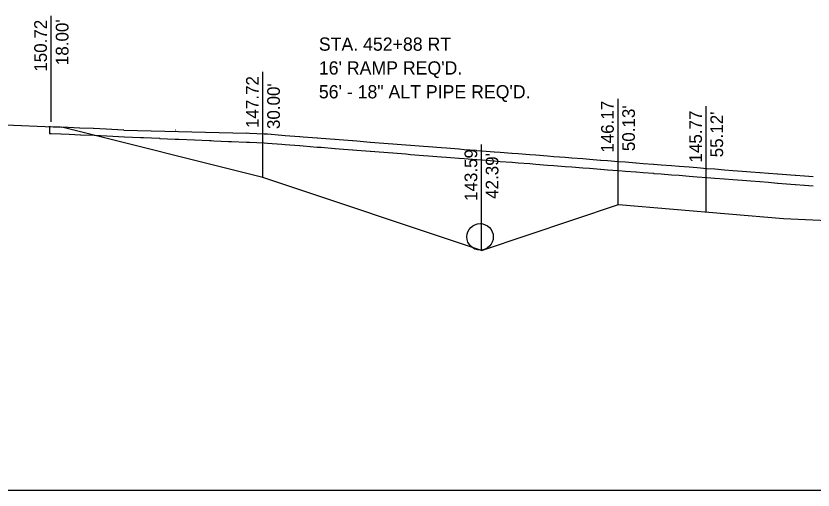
# Model space of a CAD drawing. Extents: x -100 to 4303, y -13 to 10775.
# Drawn here: x 165.99 to 211.18, y 1500 to 1526.88 of the extents above; entities that cross this region are included whole.
import ezdxf

# ---------------------------------------------------------------- set-up
doc = ezdxf.new("R2010")
doc.units = 0
for name, color, linetype in [('DTM_X_GROUND', 7, 'Continuous'), ('XS_CELL', 7, 'Continuous'), ('XS_P_DRAINAGE', 7, 'Continuous'), ('XS_P_TX_CLEARZONE', 7, 'Continuous')]:
    doc.layers.add(name, color=color, linetype=linetype)

msp = doc.modelspace()

# ---------------------------------------------------------------- linework, layer by layer
at = {"layer": 'DTM_X_GROUND'}
for p, q in [((164, 1520.754), (168.551, 1520.572)), ((167.86, 1520.599), (167.859, 1520.599)), ((167.953, 1520.596), (167.86, 1520.599)), ((167.906, 1520.598), (167.906, 1520.222)), ((168.497, 1520.574), (167.953, 1520.596)), ((167.953, 1520.596), (167.953, 1520.596)), ((167.906, 1520.222), (167.907, 1520.222)), ((167.907, 1520.222), (168, 1520.218)), ((168, 1520.218), (168, 1520.218)), ((168, 1520.218), (168.544, 1520.196)), ((168.504, 1520.574), (168.497, 1520.574)), ((168.959, 1520.555), (168.504, 1520.574)), ((168.544, 1520.196), (168.551, 1520.196)), ((168.551, 1520.196), (169.006, 1520.178)), ((169.607, 1520.522), (168.959, 1520.555)), ((169.006, 1520.178), (169.654, 1520.145)), ((169.619, 1520.521), (169.607, 1520.522)), ((170.375, 1520.49), (169.619, 1520.521)), ((169.654, 1520.145), (169.666, 1520.144)), ((169.666, 1520.144), (170.422, 1520.113)), ((170.386, 1520.49), (170.375, 1520.49)), ((171.103, 1520.46), (170.386, 1520.49)), ((172.093, 1520.407), (171.103, 1520.46)), ((172.107, 1520.406), (172.093, 1520.407)), ((172.107, 1520.406), (179.057, 1520.226)), ((175.041, 1520.402), (175.027, 1520.402)), ((179.07, 1520.226), (179.057, 1520.226)), ((179.237, 1520.219), (179.07, 1520.226)), ((180.061, 1520.183), (179.237, 1520.219)), ((180.074, 1520.182), (180.061, 1520.183)), ((180.251, 1520.168), (180.074, 1520.182)), ((181.065, 1520.104), (180.251, 1520.168)), ((170.422, 1520.113), (170.434, 1520.112)), ((170.434, 1520.112), (171.15, 1520.083)), ((171.15, 1520.083), (172.14, 1520.029)), ((172.14, 1520.029), (172.154, 1520.029)), ((172.154, 1520.029), (173.063, 1519.99)), ((173.063, 1519.99), (173.077, 1519.989)), ((173.077, 1519.989), (173.234, 1519.98)), ((173.234, 1519.98), (174.133, 1519.941)), ((174.133, 1519.941), (174.147, 1519.94)), ((174.147, 1519.94), (175.027, 1519.902)), ((175.027, 1519.902), (175.041, 1519.902)), ((175.041, 1519.902), (175.237, 1519.892)), ((175.237, 1519.892), (176.109, 1519.854)), ((176.109, 1519.854), (176.123, 1519.854)), ((176.123, 1519.854), (176.976, 1519.817)), ((176.976, 1519.817), (177.05, 1519.813)), ((177.05, 1519.813), (177.063, 1519.813)), ((177.063, 1519.813), (177.207, 1519.807)), ((177.207, 1519.807), (178.053, 1519.77)), ((178.053, 1519.77), (178.066, 1519.769)), ((178.066, 1519.769), (178.222, 1519.763)), ((178.222, 1519.763), (179.057, 1519.726)), ((179.057, 1519.726), (179.07, 1519.726)), ((179.07, 1519.726), (179.237, 1519.719)), ((179.237, 1519.719), (180.061, 1519.683)), ((180.061, 1519.683), (180.074, 1519.682)), ((180.074, 1519.682), (180.251, 1519.668)), ((181.077, 1520.103), (181.065, 1520.104)), ((181.266, 1520.089), (181.077, 1520.103)), ((182.069, 1520.026), (181.266, 1520.089)), ((182.081, 1520.025), (182.069, 1520.026)), ((182.281, 1520.009), (182.081, 1520.025)), ((183.073, 1519.947), (182.281, 1520.009)), ((183.085, 1519.946), (183.073, 1519.947)), ((183.296, 1519.93), (183.085, 1519.946)), ((184.076, 1519.869), (183.296, 1519.93)), ((184.088, 1519.868), (184.076, 1519.869)), ((184.31, 1519.851), (184.088, 1519.868)), ((185.08, 1519.79), (184.31, 1519.851)), ((185.092, 1519.789), (185.08, 1519.79)), ((185.325, 1519.771), (185.092, 1519.789)), ((186.084, 1519.712), (185.325, 1519.771)), ((186.096, 1519.711), (186.084, 1519.712)), ((186.34, 1519.692), (186.096, 1519.711)), ((187.088, 1519.633), (186.34, 1519.692)), ((180.251, 1519.668), (181.065, 1519.604)), ((181.065, 1519.604), (181.077, 1519.603)), ((181.077, 1519.603), (181.266, 1519.589)), ((181.266, 1519.589), (182.069, 1519.526)), ((182.069, 1519.526), (182.081, 1519.525)), ((182.081, 1519.525), (182.281, 1519.509)), ((182.281, 1519.509), (183.073, 1519.447)), ((183.073, 1519.447), (183.085, 1519.446)), ((183.085, 1519.446), (183.296, 1519.43)), ((183.296, 1519.43), (184.076, 1519.369)), ((184.076, 1519.369), (184.088, 1519.368)), ((184.088, 1519.368), (184.31, 1519.351)), ((184.31, 1519.351), (185.08, 1519.29)), ((185.08, 1519.29), (185.092, 1519.289)), ((185.092, 1519.289), (185.325, 1519.271)), ((185.325, 1519.271), (186.084, 1519.212)), ((187.099, 1519.632), (187.088, 1519.633)), ((187.355, 1519.612), (187.099, 1519.632)), ((188.092, 1519.555), (187.355, 1519.612)), ((188.103, 1519.554), (188.092, 1519.555)), ((188.369, 1519.533), (188.103, 1519.554)), ((189.095, 1519.476), (188.369, 1519.533)), ((189.107, 1519.475), (189.095, 1519.476)), ((189.384, 1519.454), (189.107, 1519.475)), ((190.099, 1519.398), (189.384, 1519.454)), ((190.11, 1519.397), (190.099, 1519.398)), ((190.399, 1519.374), (190.11, 1519.397)), ((191.103, 1519.319), (190.399, 1519.374)), ((191.114, 1519.319), (191.103, 1519.319)), ((191.414, 1519.295), (191.114, 1519.319)), ((192.107, 1519.241), (191.414, 1519.295)), ((192.118, 1519.24), (192.107, 1519.241)), ((192.428, 1519.216), (192.118, 1519.24)), ((186.084, 1519.212), (186.096, 1519.211)), ((186.096, 1519.211), (186.34, 1519.192)), ((186.34, 1519.192), (187.088, 1519.133)), ((187.088, 1519.133), (187.099, 1519.132)), ((187.099, 1519.132), (187.355, 1519.112)), ((187.355, 1519.112), (188.092, 1519.055)), ((188.092, 1519.055), (188.103, 1519.054)), ((188.103, 1519.054), (188.369, 1519.033)), ((188.369, 1519.033), (189.095, 1518.976)), ((189.095, 1518.976), (189.107, 1518.975)), ((189.107, 1518.975), (189.384, 1518.954)), ((189.384, 1518.954), (190.099, 1518.898)), ((190.099, 1518.898), (190.11, 1518.897)), ((190.11, 1518.897), (190.399, 1518.874)), ((190.399, 1518.874), (191.103, 1518.819)), ((191.103, 1518.819), (191.114, 1518.819)), ((191.114, 1518.819), (191.414, 1518.795)), ((191.414, 1518.795), (192.107, 1518.741)), ((193.111, 1519.162), (192.428, 1519.216)), ((193.121, 1519.162), (193.111, 1519.162)), ((193.443, 1519.136), (193.121, 1519.162)), ((194.115, 1519.084), (193.443, 1519.136)), ((194.125, 1519.083), (194.115, 1519.084)), ((194.458, 1519.057), (194.125, 1519.083)), ((195.118, 1519.005), (194.458, 1519.057)), ((195.129, 1519.005), (195.118, 1519.005)), ((195.473, 1518.978), (195.129, 1519.005)), ((196.122, 1518.927), (195.473, 1518.978)), ((196.132, 1518.926), (196.122, 1518.927)), ((196.487, 1518.898), (196.132, 1518.926)), ((197.126, 1518.848), (196.487, 1518.898)), ((197.136, 1518.848), (197.126, 1518.848)), ((197.502, 1518.819), (197.136, 1518.848)), ((198.13, 1518.77), (197.502, 1518.819)), ((192.107, 1518.741), (192.118, 1518.74)), ((192.118, 1518.74), (192.428, 1518.716)), ((192.428, 1518.716), (193.111, 1518.662)), ((193.111, 1518.662), (193.121, 1518.662)), ((193.121, 1518.662), (193.443, 1518.636)), ((193.443, 1518.636), (194.115, 1518.584)), ((194.115, 1518.584), (194.125, 1518.583)), ((194.125, 1518.583), (194.458, 1518.557)), ((194.458, 1518.557), (195.118, 1518.505)), ((195.118, 1518.505), (195.129, 1518.505)), ((195.129, 1518.505), (195.473, 1518.478)), ((195.473, 1518.478), (196.122, 1518.427)), ((196.122, 1518.427), (196.132, 1518.426)), ((196.132, 1518.426), (196.487, 1518.398)), ((196.487, 1518.398), (197.126, 1518.348)), ((197.126, 1518.348), (197.136, 1518.348)), ((197.136, 1518.348), (197.502, 1518.319)), ((198.139, 1518.769), (198.13, 1518.77)), ((198.517, 1518.74), (198.139, 1518.769)), ((199.134, 1518.691), (198.517, 1518.74)), ((199.143, 1518.691), (199.134, 1518.691)), ((199.532, 1518.66), (199.143, 1518.691)), ((200.138, 1518.613), (199.532, 1518.66)), ((200.147, 1518.612), (200.138, 1518.613)), ((200.546, 1518.581), (200.147, 1518.612)), ((201.141, 1518.534), (200.546, 1518.581)), ((201.15, 1518.534), (201.141, 1518.534)), ((201.561, 1518.502), (201.15, 1518.534)), ((202.145, 1518.456), (201.561, 1518.502)), ((202.154, 1518.455), (202.145, 1518.456)), ((202.576, 1518.422), (202.154, 1518.455)), ((203.149, 1518.377), (202.576, 1518.422)), ((203.158, 1518.377), (203.149, 1518.377)), ((203.591, 1518.343), (203.158, 1518.377)), ((204.153, 1518.299), (203.591, 1518.343)), ((197.502, 1518.319), (198.13, 1518.27)), ((198.13, 1518.27), (198.139, 1518.269)), ((198.139, 1518.269), (198.517, 1518.24)), ((198.517, 1518.24), (199.134, 1518.191)), ((199.134, 1518.191), (199.143, 1518.191)), ((199.143, 1518.191), (199.532, 1518.16)), ((199.532, 1518.16), (200.138, 1518.113)), ((200.138, 1518.113), (200.147, 1518.112)), ((200.147, 1518.112), (200.546, 1518.081)), ((200.546, 1518.081), (201.141, 1518.034)), ((201.141, 1518.034), (201.15, 1518.034)), ((201.15, 1518.034), (201.561, 1518.002)), ((201.561, 1518.002), (202.145, 1517.956)), ((202.145, 1517.956), (202.154, 1517.955)), ((202.154, 1517.955), (202.576, 1517.922)), ((202.576, 1517.922), (203.149, 1517.877)), ((203.149, 1517.877), (203.158, 1517.877)), ((203.158, 1517.877), (203.591, 1517.843)), ((204.161, 1518.298), (204.153, 1518.299)), ((204.605, 1518.263), (204.161, 1518.298)), ((205.157, 1518.22), (204.605, 1518.263)), ((205.165, 1518.22), (205.157, 1518.22)), ((205.62, 1518.184), (205.165, 1518.22)), ((206.16, 1518.142), (205.62, 1518.184)), ((206.169, 1518.141), (206.16, 1518.142)), ((206.635, 1518.105), (206.169, 1518.141)), ((207.164, 1518.063), (206.635, 1518.105)), ((207.172, 1518.063), (207.164, 1518.063)), ((207.65, 1518.025), (207.172, 1518.063)), ((208.168, 1517.985), (207.65, 1518.025)), ((208.176, 1517.984), (208.168, 1517.985)), ((208.664, 1517.946), (208.176, 1517.984)), ((209.172, 1517.906), (208.664, 1517.946)), ((209.18, 1517.906), (209.172, 1517.906)), ((209.679, 1517.867), (209.18, 1517.906)), ((203.591, 1517.843), (204.153, 1517.799)), ((204.153, 1517.799), (204.161, 1517.798)), ((204.161, 1517.798), (204.605, 1517.763)), ((204.605, 1517.763), (205.157, 1517.72)), ((205.157, 1517.72), (205.165, 1517.72)), ((205.165, 1517.72), (205.62, 1517.684)), ((205.62, 1517.684), (206.16, 1517.642)), ((206.16, 1517.642), (206.169, 1517.641)), ((206.169, 1517.641), (206.635, 1517.605)), ((206.635, 1517.605), (207.164, 1517.563)), ((207.164, 1517.563), (207.172, 1517.563)), ((207.172, 1517.563), (207.65, 1517.525)), ((207.65, 1517.525), (208.168, 1517.485)), ((208.168, 1517.485), (208.176, 1517.484)), ((208.176, 1517.484), (208.664, 1517.446)), ((208.664, 1517.446), (209.172, 1517.406)), ((210.176, 1517.828), (209.679, 1517.867)), ((210.183, 1517.827), (210.176, 1517.828)), ((210.694, 1517.787), (210.183, 1517.827)), ((211.18, 1517.749), (210.694, 1517.787)), ((211.187, 1517.749), (211.18, 1517.749)), ((209.172, 1517.406), (209.18, 1517.406)), ((209.18, 1517.406), (209.679, 1517.367)), ((209.679, 1517.367), (210.176, 1517.328)), ((210.176, 1517.328), (210.183, 1517.327)), ((210.183, 1517.327), (210.694, 1517.287)), ((210.694, 1517.287), (211.18, 1517.249)), ((211.18, 1517.249), (211.187, 1517.249))]:
    msp.add_line(p, q, dxfattribs=at)
for points in [[(192.386, 1513.59), (192.386, 1513.59), (180, 1517.719), (168.595, 1520.57)], [(192.386, 1513.59), (200.161, 1516.182)], [(200.161, 1516.182), (209.501, 1515.398), (209.508, 1515.398), (214.069, 1515.192), (233.709, 1514.282), (245.883, 1513.954), (247.772, 1513.966), (248.38, 1513.947), (266.299, 1513.788), (292.07, 1513.357), (292.103, 1513.35), (300, 1513.32)]]:
    msp.add_lwpolyline(points, dxfattribs=at)
msp.add_circle((192.308, 1514.353), 0.75, dxfattribs=at)
at = {"layer": 'XS_CELL'}
msp.add_line((150, 1500), (300, 1500), dxfattribs=at)
msp.add_line((150, 1500), (300, 1500), dxfattribs=at)
at = {"layer": 'XS_P_TX_CLEARZONE'}
for p, q in [((168, 1520.879), (168, 1526.879)), ((180, 1517.719), (180, 1523.719)), ((180, 1517.719), (180, 1523.719)), ((200.127, 1516.171), (200.127, 1522.171)), ((200.127, 1516.171), (200.127, 1522.171)), ((200.127, 1516.171), (200.127, 1522.171)), ((205.123, 1515.766), (205.123, 1521.766)), ((205.123, 1515.766), (205.123, 1521.766)), ((205.123, 1515.766), (205.123, 1521.766)), ((192.386, 1513.59), (192.386, 1519.59)), ((192.386, 1513.59), (192.386, 1519.59)), ((192.386, 1513.59), (192.386, 1519.59))]:
    msp.add_line(p, q, dxfattribs=at)

# ---------------------------------------------------------------- texts
at = {"layer": 'XS_P_DRAINAGE'}
for s, p in [('STA. 452+88 RT', (183.167, 1524.906)), ("16' RAMP REQ'D.", (183.167, 1523.556)), ('56\' - 18" ALT PIPE REQ\'D.', (183.167, 1522.206))]:
    msp.add_text(s, height=0.75, dxfattribs=at).set_placement(p)
at = {"layer": 'XS_P_TX_CLEARZONE'}
for s, p in [('150.72', (167.75, 1523.717)), ("18.00'", (168.974, 1524.09)), ('147.72', (179.76, 1520.523)), ('147.72', (179.76, 1520.523)), ("30.00'", (180.96, 1520.466)), ("30.00'", (180.96, 1520.466)), ('146.17', (199.887, 1519.122)), ('146.17', (199.887, 1519.122)), ('146.17', (199.887, 1519.122)), ("50.13'", (201.087, 1519.213)), ("50.13'", (201.087, 1519.213)), ("50.13'", (201.087, 1519.213)), ('145.77', (204.883, 1518.57)), ('145.77', (204.883, 1518.57)), ('145.77', (204.883, 1518.57)), ("55.12'", (206.083, 1518.865)), ("55.12'", (206.083, 1518.865)), ("55.12'", (206.083, 1518.865)), ('143.59', (192.146, 1516.389)), ('143.59', (192.146, 1516.389)), ('143.59', (192.146, 1516.389)), ("42.39'", (193.346, 1516.508)), ("42.39'", (193.346, 1516.508)), ("42.39'", (193.346, 1516.508))]:
    msp.add_text(s, height=0.72, rotation=90, dxfattribs=at).set_placement(p)

doc.saveas('drawing.dxf')
